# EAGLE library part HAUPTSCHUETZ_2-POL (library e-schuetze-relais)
Hauptschütz mit 2 Schließern
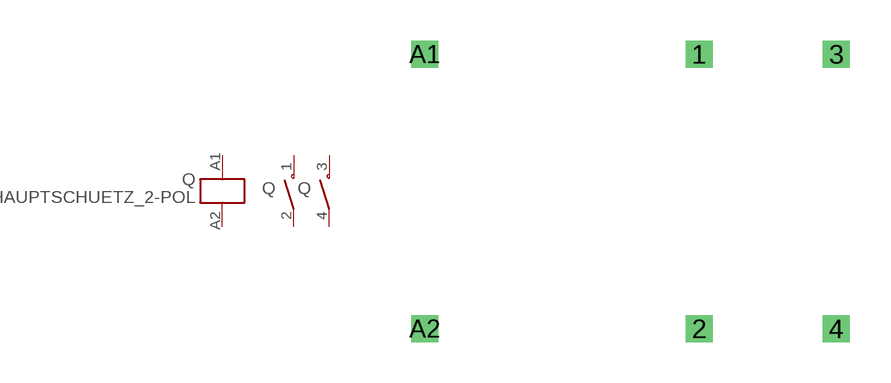
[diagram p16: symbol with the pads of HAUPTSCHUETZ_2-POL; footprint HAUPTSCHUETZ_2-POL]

Designator prefix Q; gates 1=SPULE G$1=SCHLIESSER_HAUPTSCHUETZ G$2=SCHLIESSER_HAUPTSCHUETZ

## HAUPTSCHUETZ_2-POL  [HAUPTSCHUETZ_2-POL]
1  G$1:3  pas
2  G$1:4  pas
3  G$2:3  pas
4  G$2:4  pas
A1  1:A1  in
A2  1:A2  in

## Footprint HAUPTSCHUETZ_2-POL (pad centres in mm)
Dummy
drill 0.5 pad 1 square: 1 2.54,2.54; 2 2.54,-7.62; 3 7.62,2.54; 4 7.62,-7.62; A1 -7.62,2.54; A2 -7.62,-7.62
